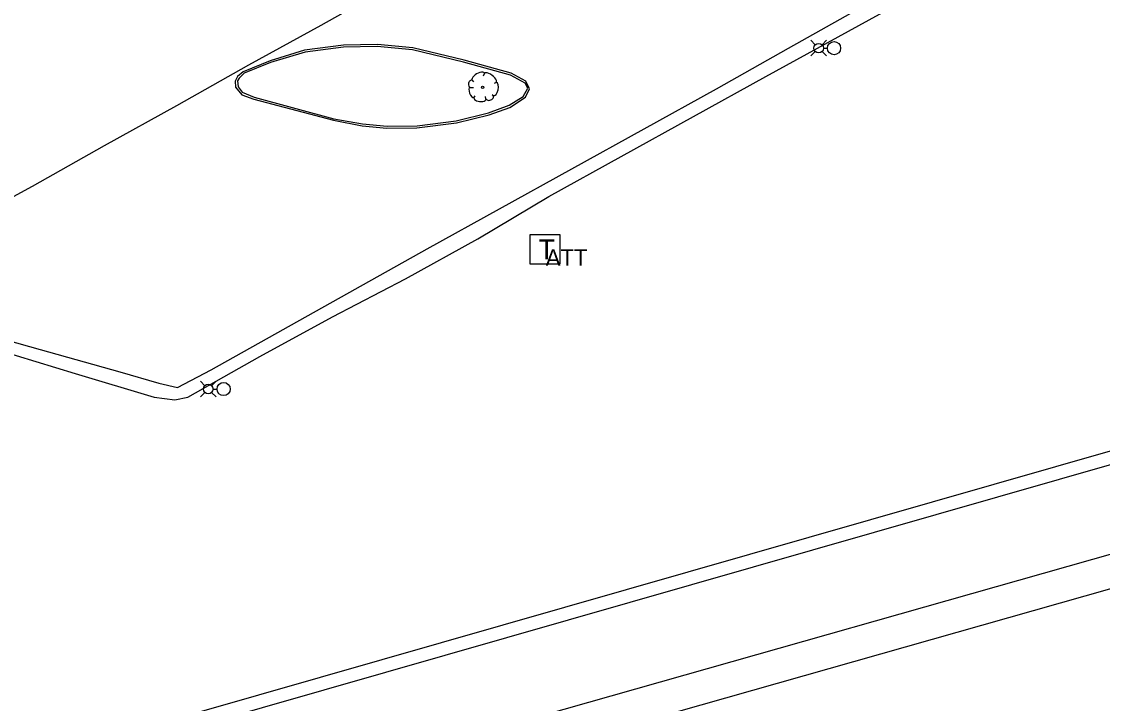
# Model space of a CAD drawing. Extents: x 1042086 to 1119166, y 1916606 to 1927565.
# Drawn here: x 1043119 to 1043446.1, y 1926040.4 to 1926246.9 of the extents above; entities that cross this region are included whole.
import ezdxf

# ---------------------------------------------------------------- set-up
doc = ezdxf.new("R2010")
doc.units = 0
for name, color, linetype in [('R_No Plot', 7, 'Continuous'), ('S_CURB', 7, 'Continuous'), ('S_EDGE_CONCRETE', 7, 'Continuous'), ('S_EDGE_PAVEMENT', 7, 'Continuous'), ('S_SHOULDER', 7, 'Continuous'), ('S_TELEPHONE_UTILITIES', 7, 'Continuous'), ('S_TELEPHONE_UTILITIES_ANNOT', 7, 'Continuous'), ('S_TREE', 7, 'Continuous'), ('S_UTILITY_POLE', 7, 'Continuous')]:
    doc.layers.add(name, color=color, linetype=linetype)

msp = doc.modelspace()

# ---------------------------------------------------------------- linework, layer by layer
at = {"layer": 'R_No Plot'}
for points in [[(1042689.29, 1925878.43), (1042715.3, 1925889.01), (1042786.05, 1925916.1), (1042812.63, 1925925.48), (1042941.44, 1925969.37), (1043015.18, 1925991.88), (1043060.81, 1926005.81), (1043635.81, 1926170.59), (1043670.05, 1926180.4), (1043718.33, 1926195.32), (1043745.92, 1926203.85), (1043769.29, 1926212.01), (1043825.81, 1926231.74)], [(1042551.38, 1925812.55), (1042620.28, 1925844.55), (1042681.9, 1925871.1), (1042716.77, 1925885.29), (1042787.43, 1925912.34), (1042813.94, 1925921.7), (1042942.67, 1925965.57), (1043016.35, 1925988.06), (1043061.94, 1926001.97), (1043636.91, 1926166.74), (1043671.19, 1926176.56), (1043719.51, 1926191.5), (1043747.17, 1926200.05), (1043770.61, 1926208.23), (1043827.19, 1926227.99)], [(1042275.41, 1925630.96), (1042382.03, 1925695.61), (1042434.36, 1925723.96), (1042497.68, 1925758.26), (1042554.68, 1925785.59), (1042668.32, 1925837.75), (1042737.66, 1925866.69), (1042841.32, 1925904.83), (1042910.61, 1925929.07), (1043049.48, 1925972.27), (1043283.15, 1926038.65), (1043631.63, 1926137.66), (1043741.19, 1926171.43), (1043807.78, 1926193.91), (1043846.36, 1926208.43)], [(1042280.59, 1925622.4), (1042387.01, 1925686.94), (1042439.13, 1925715.17), (1042502.23, 1925749.35), (1042558.93, 1925776.54), (1042672.33, 1925828.59), (1042741.31, 1925857.38), (1042844.7, 1925895.42), (1042913.75, 1925919.57), (1043052.33, 1925962.68), (1043285.88, 1926029.03), (1043634.47, 1926128.07), (1043744.26, 1926161.91), (1043811.14, 1926184.5), (1043849.96, 1926199.1)]]:
    msp.add_lwpolyline(points, dxfattribs=at)
at = {"layer": 'S_CURB'}
msp.add_lwpolyline([(1043184.3, 1926228.91), (1043184.55, 1926227.11), (1043185.81, 1926225.5), (1043189.4, 1926224.04), (1043213.48, 1926217.45), (1043222.22, 1926215.9), (1043229.67, 1926215.24), (1043238.73, 1926215.35), (1043250.48, 1926216.88), (1043260.28, 1926219.23), (1043266.55, 1926221.62), (1043270.77, 1926224.18), (1043272.16, 1926226.7), (1043271.44, 1926228.2), (1043266.98, 1926230.66), (1043252.78, 1926234.58), (1043237.26, 1926238.38), (1043226.66, 1926239.34), (1043216.45, 1926239.16), (1043204.78, 1926237.59), (1043194.38, 1926234.54), (1043186.39, 1926231.26), (1043184.81, 1926229.71)], close=True, dxfattribs=at)
at = {"layer": 'S_EDGE_CONCRETE'}
msp.add_lwpolyline([(1043062.59, 1926163.39), (1043070.11, 1926162.59), (1043076.35, 1926160.83), (1043100.56, 1926154.41), (1043124.63, 1926147.59), (1043148.74, 1926140.86), (1043160.51, 1926137.4), (1043166.21, 1926136.12), (1043176.34, 1926141.45), (1043198.18, 1926153.61), (1043219.97, 1926165.88), (1043241.79, 1926178.09), (1043263.67, 1926190.21), (1043285.53, 1926202.34), (1043307.43, 1926214.4), (1043329.32, 1926226.49), (1043351.07, 1926238.83), (1043372.48, 1926250.87), (1043394.36, 1926262.95), (1043416.28, 1926274.96), (1043438.14, 1926287.07), (1043459.9, 1926299.36)], dxfattribs=at)
msp.add_lwpolyline([(1043183.63, 1926228.84), (1043183.76, 1926227.03), (1043185.62, 1926224.69), (1043189.25, 1926223.4), (1043213.37, 1926217.01), (1043222.08, 1926215.32), (1043229.52, 1926214.61), (1043238.59, 1926214.75), (1043250.66, 1926216.27), (1043260.46, 1926218.64), (1043266.77, 1926220.9), (1043271.48, 1926223.96), (1043272.75, 1926226.52), (1043271.62, 1926228.89), (1043267.14, 1926231.25), (1043252.96, 1926235.23), (1043237.41, 1926238.94), (1043226.69, 1926239.94), (1043216.47, 1926239.76), (1043204.6, 1926238.23), (1043194.24, 1926235.03), (1043186.02, 1926231.71), (1043184.35, 1926230.27)], close=True, dxfattribs=at)
at = {"layer": 'S_EDGE_PAVEMENT'}
msp.add_lwpolyline([(1043102.91, 1926186.56), (1043122.35, 1926197.07), (1043144.15, 1926209.32), (1043166.01, 1926221.45), (1043187.73, 1926233.83), (1043209.7, 1926245.77), (1043231.46, 1926258.09), (1043253.4, 1926270.06), (1043275.25, 1926282.23), (1043297.21, 1926294.17), (1043326.74, 1926310.95), (1043348.54, 1926323.19), (1043370.32, 1926335.48), (1043392.17, 1926347.63), (1043414.02, 1926359.78), (1043436.24, 1926372.23), (1043453.57, 1926381.87)], dxfattribs=at)
at = {"layer": 'S_SHOULDER'}
msp.add_lwpolyline([(1043063.59, 1926160.64), (1043087.45, 1926154.94), (1043111.32, 1926147.65), (1043135.23, 1926140.3), (1043159.13, 1926133.15), (1043165.36, 1926132.35), (1043169.27, 1926133.12), (1043191.11, 1926145.48), (1043213.08, 1926157.45), (1043235.23, 1926169.04), (1043257.1, 1926181.11), (1043278.59, 1926193.91), (1043300.44, 1926206.03), (1043322.31, 1926218.15), (1043344.25, 1926230.22), (1043366.13, 1926242.27), (1043387.95, 1926254.4), (1043409.64, 1926266.81), (1043431.5, 1926278.96), (1043453.48, 1926290.94)], dxfattribs=at)
at = {"layer": 'S_TELEPHONE_UTILITIES'}
msp.add_lwpolyline([(1043272.9, 1926173.43), (1043272.9, 1926182.43), (1043281.9, 1926182.43), (1043281.9, 1926173.43)], close=True, dxfattribs=at)
at = {"layer": 'S_TREE'}
for p, q in [((1043259.08, 1926231.24), (1043258.69, 1926230.38)), ((1043254.62, 1926226.9), (1043255.75, 1926226.9)), ((1043255.28, 1926229.22), (1043255.79, 1926228.64)), ((1043262.64, 1926228.45), (1043261.99, 1926228.17)), ((1043255.79, 1926223.72), (1043256.25, 1926224.42)), ((1043259.47, 1926223.45), (1043259.39, 1926224.22)), ((1043261.87, 1926224.34), (1043261.4, 1926224.76))]:
    msp.add_line(p, q, dxfattribs=at)
msp.add_circle((1043258.52, 1926226.99), 0.341, dxfattribs=at)
for centre, major_axis, ratio, start_param, end_param in [((1043257.19, 1926230.19), (1.86, 1.08), 0.471018, 0, 3.141593), ((1043260.84, 1926229.87), (-1.81, 1.36), 0.405113, 3.141593, 6.283186), ((1043254.95, 1926228.08), (0.31, 1.03), 0.646762, 0, 3.141593), ((1043255.26, 1926225.43), (-0.61, 1.6), 0.420543, 6.283185, 9.424777), ((1043262.2, 1926226.46), (0.46, 2.04), 0.482994, 3.141593, 6.283185), ((1043257.72, 1926223.65), (-1.83, 0.19), 0.529943, 0, 3.141593), ((1043260.67, 1926223.94), (1.09, 0.46), 0.711534, 3.141592, 6.283185)]:
    msp.add_ellipse(centre, major_axis=major_axis, ratio=ratio, start_param=start_param, end_param=end_param, dxfattribs=at)
at = {"layer": 'S_UTILITY_POLE'}
for p, q in [((1043359.2, 1926239.85), (1043357.83, 1926241.22)), ((1043361.22, 1926239.85), (1043362.58, 1926241.22)), ((1043357.83, 1926236.47), (1043359.2, 1926237.83)), ((1043362.58, 1926236.47), (1043361.22, 1926237.83)), ((1043361.63, 1926238.84), (1043362.85, 1926238.84)), ((1043174.5, 1926136.65), (1043173.14, 1926138.01)), ((1043176.52, 1926136.65), (1043177.89, 1926138.01)), ((1043176.94, 1926135.64), (1043178.16, 1926135.64)), ((1043173.14, 1926133.26), (1043174.5, 1926134.63)), ((1043177.89, 1926133.26), (1043176.52, 1926134.63))]:
    msp.add_line(p, q, dxfattribs=at)
for centre, radius in [((1043360.21, 1926238.84), 1.43), ((1043364.86, 1926238.84), 2), ((1043175.51, 1926135.64), 1.43), ((1043180.16, 1926135.64), 2)]:
    msp.add_circle(centre, radius, dxfattribs=at)

# ---------------------------------------------------------------- texts
at = {"layer": 'S_TELEPHONE_UTILITIES'}
msp.add_text('T', height=6, rotation=360, dxfattribs=at).set_placement((1043275.46, 1926174.93))
at = {"layer": 'S_TELEPHONE_UTILITIES_ANNOT'}
msp.add_text('ATT', height=5, dxfattribs=at).set_placement((1043277.62, 1926172.95))

doc.saveas('drawing.dxf')
